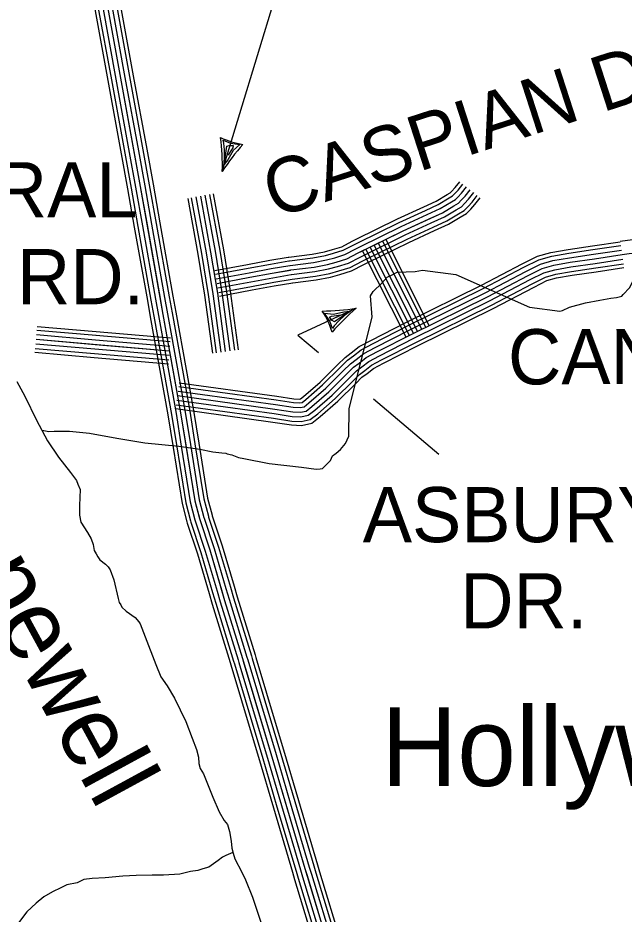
# Model space of a CAD drawing. Extents: x 1551132 to 1791609, y 378168 to 563823.
# Drawn here: x 1653929 to 1657991, y 420262 to 426270 of the extents above; entities that cross this region are included whole.
import ezdxf

# ---------------------------------------------------------------- set-up
doc = ezdxf.new("R2010")
doc.units = 0
for name, color, linetype in [('DESIGN - DRAINAGE - Bridges and Cross Drains Size Text', 7, 'Continuous'), ('DESIGN - ROW - Right-of-Way and Easement Labels', 7, 'Continuous'), ('DESIGN - TRANSPORTATION - Text', 7, 'Continuous'), ('SURVEY - CENTERLINE - Preliminary Text', 7, 'Continuous'), ('SURVEY - PROPERTY - Owners', 7, 'Continuous'), ('SURVEY - TRANSPORTATION - Roads', 7, 'Continuous'), ('SURVEY - VEGETATION - Features with Text', 7, 'Continuous')]:
    doc.layers.add(name, color=color, linetype=linetype)

msp = doc.modelspace()

# ---------------------------------------------------------------- linework, layer by layer
at = {"layer": 'DESIGN - ROW - Right-of-Way and Easement Labels'}
for p, q in [((1655298.56, 425240.72), (1655734.434, 426681.149)), ((1655309.568, 425429.383), (1655304.785, 425449.717)), ((1655304.785, 425449.717), (1655353.1, 425430.241)), ((1655313.501, 425384.948), (1655309.568, 425429.383)), ((1655311.834, 425286.729), (1655328.351, 425411.391)), ((1655313.943, 425332.655), (1655313.501, 425384.948)), ((1655328.351, 425411.391), (1655344.975, 425415.074)), ((1655370.875, 425380.39), (1655336.292, 425319.03)), ((1655351.584, 425371.965), (1655338.342, 425350.556)), ((1655344.975, 425415.074), (1655372.508, 425414.258)), ((1655370.125, 425399.474), (1655351.584, 425371.965)), ((1655353.1, 425430.241), (1655415.557, 425420.841)), ((1655372.508, 425414.258), (1655370.125, 425399.474)), ((1655415.557, 425420.841), (1655370.875, 425380.39)), ((1655309.085, 425274.312), (1655313.943, 425332.655)), ((1655336.292, 425319.03), (1655311.834, 425286.729)), ((1656019.042, 424237.76), (1655984.202, 424290.445)), ((1655984.202, 424290.445), (1656044.158, 424284.345)), ((1656044.158, 424284.345), (1656112.89, 424299.745)), ((1656153.256, 424303.212), (1656049.608, 424232.002)), ((1656112.89, 424299.745), (1656153.256, 424303.212)), ((1656164.314, 424309.479), (1656117.74, 424274.02)), ((1656017.917, 424262.878), (1656030.492, 424271.011)), ((1656035.742, 424241.885), (1656017.917, 424262.878)), ((1656036.925, 424188.834), (1656019.042, 424237.76)), ((1656030.492, 424271.011), (1656063.333, 424275.653)), ((1656049.608, 424232.002), (1656035.742, 424241.885)), ((1656079.191, 424238.677), (1656048.817, 424206.001)), ((1656063.333, 424275.653), (1656088.099, 424280.161)), ((1656117.74, 424274.02), (1656079.191, 424238.677)), ((1656048.817, 424206.001), (1656036.925, 424188.834))]:
    msp.add_line(p, q, dxfattribs=at)
for points in [[(1656196.313, 424324.154), (1655805.639, 424143.799), (1655943.352, 424027.246)], [(1656311.244, 423715.905), (1656749.608, 423344.921)]]:
    msp.add_lwpolyline(points, dxfattribs=at)
for centre, radius, start, end in [((1653746.777, 425280.525), 1552.315, 358.5310611, 6.9588389), ((1655518.373, 425948.283), 532.286, 244.313675, 261.1720722), ((1656467.354, 424495.075), 1386.374, 138.0242889, 147.4628278), ((1655967.543, 425691.491), 1386.33, 270.0587833, 279.4973222), ((1655523.589, 424013.634), 532.306, 16.3489444, 33.2073417), ((1657205.819, 423145.003), 1552.278, 130.5682417, 138.9960194)]:
    msp.add_arc(centre, radius, start, end, dxfattribs=at)
at = {"layer": 'DESIGN - TRANSPORTATION - Text'}
for points in [[(1656640.203, 424579.503), (1656863.748, 424550.394), (1657358.069, 424329.972), (1657561.49, 424303.371), (1657579.006, 424309.263), (1657625.146, 424330.972), (1657733.336, 424360.256), (1657829.442, 424377.598), (1657903.532, 424391.099), (1657939.547, 424394.849), (1657975.613, 424404.607), (1657985.688, 424416.558), (1658027.979, 424460.334), (1658050.253, 424502.243), (1658056.628, 424525.502), (1658049.003, 424590.971)], [(1656292.144, 424406.415), (1656310.486, 424436.216), (1656366.843, 424491.909), (1656403.109, 424531.718), (1656437.208, 424547.502), (1656471.324, 424565.286), (1656591.354, 424570.444), (1656640.203, 424579.503)], [(1654090.445, 423505.798), (1654137.103, 423497.032), (1654171.11, 423498.798), (1654213.126, 423500.507), (1654275.116, 423500.065), (1654409.03, 423487.098), (1654590.792, 423451.747), (1654778.588, 423422.372), (1655006.432, 423398.721), (1655148.296, 423379.687), (1655236.177, 423361.037), (1655296.125, 423354.595), (1655322.117, 423352.412), (1655332.091, 423348.337), (1655362.032, 423340.111), (1655407.923, 423323.761), (1655443.872, 423315.486), (1655611.643, 423282.252), (1655829.48, 423258.668), (1655927.386, 423243.951), (1655955.41, 423247.759), (1655969.418, 423249.659), (1655987.534, 423267.56), (1656023.767, 423303.361), (1656037.966, 423333.312), (1656062.083, 423351.17), (1656090.249, 423377.013), (1656124.506, 423416.839), (1656145.539, 423465.957), (1656149.072, 423650.837), (1656303.919, 424264.444), (1656292.144, 424406.415)], [(1653922.075, 423831.624), (1653975.44, 423735.088), (1654054.38, 423574.267), (1654127.47, 423435.522), (1654200.743, 423324.827), (1654282.066, 423222.083), (1654321.723, 423169.715), (1654329.548, 423143.622), (1654345.331, 423109.455), (1654340.623, 423001.31), (1654342.198, 422937.192), (1654349.881, 422889.057), (1654395.438, 422820.631), (1654419.154, 422778.388), (1654432.904, 422740.228), (1654440.645, 422700.111), (1654452.495, 422677.994), (1654464.37, 422657.876), (1654478.236, 422637.742), (1654516.035, 422607.425), (1654533.918, 422589.266), (1654547.784, 422569.141), (1654571.35, 422502.864), (1654600.533, 422378.452), (1654606.349, 422350.368), (1654618.257, 422336.26), (1654626.149, 422320.176), (1654653.965, 422291.934)], [(1654653.965, 422291.934), (1654715.68, 422249.432), (1654739.496, 422221.215), (1654747.404, 422207.14), (1654780.837, 422120.762), (1654853.627, 421935.941), (1654887.068, 421851.572), (1654928.675, 421791.179), (1654978.132, 421708.693), (1655055.114, 421553.898), (1655096.379, 421441.42), (1655125.878, 421365.084), (1655139.536, 421312.908), (1655141.261, 421270.824), (1655151.044, 421238.706), (1655172.811, 421202.489), (1655235.784, 421045.793), (1655277.133, 420947.34), (1655310.749, 420889.005), (1655332.582, 420862.805), (1655338.473, 420846.738), (1655346.265, 420814.628), (1655357.839, 420750.443), (1655363.539, 420704.334), (1655371.314, 420670.216), (1655383.064, 420632.074), (1655430.488, 420543.596), (1655454.145, 420491.345), (1655500.719, 420374.917)], [(1655370.239, 420674.916), (1655323.215, 420654.533), (1655299.141, 420642.682), (1655271, 420620.848), (1655208.709, 420577.222), (1655168.635, 420565.48), (1655134.561, 420553.705), (1655086.529, 420548.038), (1655014.397, 420528.512), (1654904.366, 420523.287), (1654828.36, 420521.82), (1654722.362, 420520.57), (1654632.323, 420515.195), (1654514.267, 420506.02), (1654426.236, 420500.636), (1654370.187, 420493.019), (1654326.047, 420471.294), (1654255.965, 420457.768), (1654215.833, 420438.018), (1654159.659, 420410.375), (1654103.452, 420378.716), (1654051.17, 420335.015), (1653988.788, 420277.364), (1653851.608, 420096.042)], [(1655500.719, 420374.917), (1655690.564, 419808.285)]]:
    msp.add_lwpolyline(points, dxfattribs=at)
at = {"layer": 'SURVEY - CENTERLINE - Preliminary Text'}
for points in [[(1654441.18, 426342.44), (1654530.686, 425850.51)], [(1654465.497, 426346.865), (1654555.003, 425854.935)], [(1654495.996, 426352.415), (1654585.502, 425860.485)], [(1654526.495, 426357.965), (1654748.123, 425139.85), (1654901.16, 424281.019), (1655019.357, 423622.835), (1655113.938, 423032.953), (1655147.22, 422906.475), (1655214.094, 422703.62), (1655314.191, 422364.261), (1655434.022, 421974.676), (1655624.458, 421338.109), (1655852.144, 420567.031), (1656034.773, 419964.59)], [(1654526.495, 426357.965), (1654616.001, 425866.036)], [(1654556.994, 426363.515), (1654646.5, 425871.586)], [(1654587.494, 426369.065), (1654677, 425877.136)], [(1654612.793, 426373.666), (1654702.299, 425881.736)], [(1654554.994, 425854.952), (1654644.5, 425363.014)], [(1654585.493, 425860.502), (1654674.999, 425368.564)], [(1654615.993, 425866.052), (1654705.499, 425374.114)], [(1654646.492, 425871.602), (1654735.998, 425379.665)], [(1654676.991, 425877.153), (1654766.497, 425385.215)], [(1654702.291, 425881.753), (1654791.797, 425389.815)], [(1654530.678, 425850.527), (1654620.184, 425358.589)], [(1654705.499, 425374.131), (1654748.123, 425139.85), (1654794.063, 424882.027)], [(1654735.998, 425379.681), (1654778.63, 425145.342), (1654824.579, 424887.468)], [(1654766.497, 425385.231), (1654809.138, 425150.842), (1654855.103, 424892.902)], [(1654791.797, 425389.832), (1654834.446, 425155.392), (1654880.419, 424897.419)], [(1654620.184, 425358.606), (1654662.783, 425124.483), (1654708.69, 424866.809)], [(1654644.5, 425363.031), (1654687.107, 425128.858), (1654733.023, 424871.151)], [(1654674.999, 425368.581), (1654717.615, 425134.358), (1654763.547, 424876.585)], [(1654855.103, 424892.919), (1654942.818, 424400.664)], [(1654880.419, 424897.435), (1654968.134, 424405.181)], [(1654708.69, 424866.826), (1654796.404, 424374.572)], [(1654733.023, 424871.168), (1654820.737, 424378.913)], [(1654763.547, 424876.601), (1654851.261, 424384.347)], [(1654794.063, 424882.043), (1654881.777, 424389.789)], [(1654824.579, 424887.485), (1654912.293, 424395.231)], [(1654796.404, 424374.597), (1654815.804, 424265.752), (1654884.66, 423882.309)], [(1654820.737, 424378.93), (1654840.128, 424270.102), (1654908.985, 423886.676)], [(1654851.261, 424384.364), (1654870.644, 424275.561), (1654939.501, 423892.151)], [(1654881.777, 424389.805), (1654901.16, 424281.019), (1654970.008, 423897.634)], [(1654912.293, 424395.247), (1654931.676, 424286.478), (1655000.516, 423903.118)], [(1654942.818, 424400.681), (1654962.192, 424291.936), (1655031.032, 423908.593)], [(1654968.134, 424405.189), (1654987.508, 424296.47), (1655056.34, 423913.143)], [(1654884.66, 423882.325), (1654933.867, 423608.302), (1654968.692, 423391.088)], [(1654908.985, 423886.692), (1654958.234, 423612.443), (1654993.099, 423395.004)], [(1654939.501, 423892.167), (1654988.791, 423617.643), (1655023.707, 423399.913)], [(1654970.008, 423897.651), (1655019.357, 423622.835), (1655054.315, 423404.821)], [(1655000.516, 423903.134), (1655049.923, 423628.027), (1655084.922, 423409.73)], [(1655031.032, 423908.609), (1655080.481, 423633.227), (1655115.53, 423414.638)], [(1655056.34, 423913.151), (1655105.838, 423637.536), (1655140.921, 423418.713)], [(1654968.683, 423391.104), (1655028.99, 423015.011), (1655061.481, 422891.574)], [(1654993.091, 423395.021), (1655053.206, 423020.12), (1655085.38, 422897.858)], [(1655023.699, 423399.929), (1655083.572, 423026.536), (1655115.363, 422905.75)], [(1655054.306, 423404.838), (1655113.938, 423032.953), (1655145.337, 422913.642)], [(1655084.914, 423409.746), (1655144.304, 423039.37), (1655175.311, 422921.534)], [(1655115.521, 423414.655), (1655174.67, 423045.787), (1655205.294, 422929.426)], [(1655140.912, 423418.73), (1655199.861, 423051.104), (1655230.16, 422935.967)], [(1655145.329, 422913.658), (1655147.22, 422906.475), (1655214.094, 422703.62), (1655293.025, 422436.021)], [(1655175.303, 422921.55), (1655176.953, 422915.283), (1655243.685, 422712.862), (1655322.758, 422444.788)], [(1655205.286, 422929.451), (1655206.694, 422924.092), (1655273.284, 422722.103), (1655352.49, 422453.563)], [(1655230.152, 422936.001), (1655231.36, 422931.401), (1655297.833, 422729.77), (1655377.156, 422460.838)], [(1655061.472, 422891.574), (1655064.039, 422881.833), (1655131.312, 422677.769), (1655209.852, 422411.487)], [(1655085.372, 422897.866), (1655087.747, 422888.858), (1655154.903, 422685.136), (1655233.56, 422418.479)], [(1655115.354, 422905.767), (1655117.488, 422897.666), (1655184.503, 422694.378), (1655263.292, 422427.254)], [(1655293.017, 422436.038), (1655314.191, 422364.261), (1655434.022, 421974.676), (1655439.055, 421957.833)], [(1655322.749, 422444.813), (1655343.874, 422373.203), (1655463.687, 421983.668), (1655468.754, 421966.709)], [(1655352.482, 422453.58), (1655373.556, 422382.145), (1655493.353, 421992.668), (1655498.453, 421975.584)], [(1655377.148, 422460.855), (1655398.181, 422389.57), (1655517.961, 422000.126), (1655523.094, 421982.951)], [(1655209.844, 422411.495), (1655231.16, 422339.243), (1655351.04, 421949.508), (1655355.973, 421932.999)], [(1655233.551, 422418.495), (1655254.826, 422346.377), (1655374.69, 421956.683), (1655379.656, 421940.083)], [(1655263.284, 422427.262), (1655284.509, 422355.319), (1655404.356, 421965.684), (1655409.355, 421948.958)], [(1655409.355, 421948.967), (1655552.66, 421469.937)], [(1655439.055, 421957.85), (1655582.359, 421478.821)], [(1655468.754, 421966.734), (1655612.059, 421487.705)], [(1655498.453, 421975.617), (1655641.758, 421496.588)], [(1655523.086, 421982.993), (1655666.391, 421503.963)], [(1655355.982, 421932.991), (1655499.286, 421453.962)], [(1655379.656, 421940.083), (1655522.961, 421461.054)], [(1655552.66, 421469.954), (1655594.742, 421329.275), (1655694.732, 420990.658)], [(1655582.359, 421478.838), (1655624.458, 421338.109), (1655724.464, 420999.442)], [(1655612.059, 421487.721), (1655654.174, 421346.943), (1655754.197, 421008.225)], [(1655641.758, 421496.605), (1655683.89, 421355.776), (1655783.921, 421017.001)], [(1655666.391, 421503.98), (1655708.54, 421363.101), (1655808.587, 421024.284)], [(1655499.286, 421453.979), (1655541.335, 421313.4), (1655641.299, 420974.883)], [(1655522.961, 421461.07), (1655565.026, 421320.442), (1655665.007, 420981.883)], [(1655694.723, 420990.675), (1655822.445, 420558.147), (1655836.728, 420511.029)], [(1655724.456, 420999.458), (1655852.144, 420567.031), (1655866.394, 420520.021)], [(1655754.189, 421008.242), (1655881.844, 420575.914), (1655896.06, 420529.013)], [(1655783.913, 421017.017), (1655911.543, 420584.806), (1655925.726, 420538.005)], [(1655808.579, 421024.301), (1655936.176, 420592.173), (1655950.334, 420545.472)], [(1655641.291, 420974.899), (1655769.071, 420542.171), (1655783.413, 420494.862)], [(1655664.999, 420981.9), (1655792.746, 420549.255), (1655807.062, 420502.037)], [(1655836.728, 420511.046), (1655981.783, 420032.533)], [(1655866.394, 420520.038), (1656011.449, 420041.525)], [(1655896.06, 420529.03), (1656041.115, 420050.517)], [(1655925.726, 420538.021), (1656070.781, 420059.509)], [(1655950.334, 420545.488), (1656095.388, 420066.976)], [(1655783.413, 420494.879), (1655928.467, 420016.366)], [(1655807.062, 420502.054), (1655952.117, 420023.541)]]:
    msp.add_lwpolyline(points, dxfattribs=at)
at = {"layer": 'SURVEY - PROPERTY - Owners'}
for points in [[(1657964.355, 424772.95), (1658014.254, 424780.417), (1658101.669, 424790.234), (1658172.984, 424790.551), (1658272.29, 424788.034), (1658429.636, 424777.117), (1658675.664, 424752.184), (1658958.682, 424743.975), (1659039.614, 424743.975), (1659192.935, 424744.025), (1659357.473, 424739.192), (1659484.203, 424726.35), (1659666.682, 424709.65), (1659783.313, 424701.483), (1659841.311, 424702.991), (1659885.194, 424707.675), (1659971.65, 424729.784), (1660129.38, 424799.386), (1660295.743, 424880.838), (1660430.006, 424974.674)], [(1657977.772, 424683.24), (1658026.029, 424690.457), (1658106.944, 424699.549), (1658172.034, 424699.832), (1658267.998, 424697.407), (1658421.92, 424686.723), (1658669.772, 424661.606), (1658957.365, 424653.264), (1659039.63, 424653.264), (1659191.618, 424653.315), (1659351.565, 424648.615), (1659475.495, 424636.056), (1659659.382, 424619.231), (1659781.321, 424610.689), (1659847.32, 424612.406), (1659901.327, 424618.172), (1660001.399, 424643.765), (1660167.645, 424717.125), (1660341.941, 424802.461)]]:
    msp.add_lwpolyline(points, dxfattribs=at)
at = {"layer": 'SURVEY - TRANSPORTATION - Roads'}
for points in [[(1656648.62, 425003.322), (1656732.309, 425041.907), (1656805.583, 425085.9), (1656826.282, 425097.433), (1656835.124, 425107.192), (1656858.948, 425132.684), (1656889.497, 425172.002)], [(1656659.386, 424979.963), (1656744.351, 425019.14), (1656818.466, 425063.632), (1656842.499, 425077.033), (1656854.048, 425089.775), (1656878.539, 425115.975), (1656909.805, 425156.227)], [(1656672.361, 424951.813), (1656758.859, 424991.697), (1656833.999, 425036.798), (1656862.04, 425052.432), (1656876.856, 425068.774), (1656902.147, 425095.842), (1656934.28, 425137.201)], [(1655321.075, 424034.088), (1655267.618, 424424.215), (1655222.695, 424700.722), (1655154.163, 425075.449)], [(1655321.075, 424034.088), (1655267.618, 424424.215), (1655222.695, 424700.722), (1655154.163, 425075.449)], [(1655351.791, 424038.296), (1655298.276, 424428.807), (1655253.244, 424705.997), (1655184.654, 425081.024)], [(1655382.499, 424042.505), (1655328.942, 424433.398), (1655283.793, 424711.272), (1655215.153, 425086.607)], [(1655407.982, 424045.997), (1655354.375, 424437.207), (1655309.134, 424715.647), (1655240.444, 425091.232)], [(1655263.869, 424490.3), (1655483.98, 424531.384), (1655632.052, 424558.769), (1655758.107, 424580.244), (1655914.153, 424599.586), (1656004.201, 424617.212), (1656062.242, 424632.979), (1656132.315, 424654.696), (1656208.446, 424694.406), (1656510.956, 424843.251), (1656773.367, 424964.246), (1656849.523, 425009.964), (1656881.589, 425027.84), (1656899.664, 425047.782), (1656925.763, 425075.708), (1656958.762, 425118.184)], [(1656685.344, 424923.662), (1656773.367, 424964.246), (1656849.523, 425009.964), (1656881.589, 425027.84), (1656899.664, 425047.782), (1656925.763, 425075.708), (1656958.762, 425118.184)], [(1656698.327, 424895.511), (1656787.875, 424936.796), (1656865.048, 424983.13), (1656901.139, 425003.248), (1656922.472, 425026.79), (1656949.379, 425055.574), (1656983.245, 425099.167)], [(1656711.301, 424867.361), (1656802.383, 424909.353), (1656880.581, 424956.296), (1656920.68, 424978.647), (1656945.279, 425005.789), (1656972.987, 425035.44), (1657007.72, 425080.141)], [(1655235.161, 424022.313), (1655181.854, 424411.373), (1655137.238, 424685.963), (1655068.865, 425059.848)], [(1655259.652, 424025.671), (1655206.295, 424415.031), (1655161.596, 424690.172), (1655093.173, 425064.29)], [(1655290.359, 424029.879), (1655236.961, 424419.623), (1655192.145, 424695.447), (1655123.672, 425069.873)], [(1656721.651, 424844.91), (1656813.957, 424887.469), (1656892.964, 424934.896), (1656936.263, 424959.038), (1656963.471, 424989.056), (1656991.812, 425019.381), (1657027.236, 425064.983)], [(1656195.922, 424786.008), (1656473.224, 424922.445), (1656648.636, 425003.331)], [(1656207.272, 424762.933), (1656484.29, 424899.228), (1656659.403, 424979.972)], [(1656220.963, 424735.115), (1656497.623, 424871.244), (1656672.377, 424951.821)], [(1656234.646, 424707.298), (1656510.956, 424843.251), (1656685.36, 424923.67)], [(1656248.329, 424679.48), (1656524.289, 424815.259), (1656698.343, 424895.52)], [(1656262.02, 424651.663), (1656537.622, 424787.275), (1656711.318, 424867.369)], [(1656272.928, 424629.487), (1656548.255, 424764.958), (1656721.668, 424844.918)], [(1655741.124, 424666.338), (1655745.399, 424667.063), (1655900.32, 424686.264), (1655984.252, 424702.689), (1656037.751, 424717.223), (1656098.782, 424736.14), (1656168.797, 424772.658), (1656195.939, 424786.016)], [(1656662.936, 424197.518), (1656371.634, 424775.366)], [(1656685.893, 424209.093), (1656394.592, 424786.942)], [(1655002.974, 423768.406), (1655655.017, 423678.329), (1655773.523, 423660.003), (1655819.53, 423657.862), (1655847.004, 423663.595), (1655878.779, 423688.496), (1655991.768, 423786.915), (1656109.482, 423903.818), (1656157.306, 423951.311), (1656196.855, 423980.245), (1656246.704, 424019.421), (1656323.518, 424060.572), (1656554.38, 424177.934), (1657061.06, 424427.916), (1657333.412, 424570.811), (1657430.518, 424619.946), (1657512.966, 424642.847), (1657624.972, 424662.731), (1657787.443, 424686.115), (1657973.188, 424713.899)], [(1655007.216, 423799.115), (1655659.509, 423709.005), (1655776.623, 423690.887), (1655817.047, 423689.012), (1655833.588, 423692.463), (1655859.029, 423712.405), (1655970.643, 423809.632), (1656087.632, 423925.81), (1656137.114, 423974.953), (1656178.122, 424004.946), (1656229.679, 424045.464), (1656309.169, 424088.057), (1656540.497, 424205.651), (1657046.993, 424455.542), (1657319.212, 424598.37), (1657419.268, 424648.989), (1657506.091, 424673.106), (1657620.055, 424693.348), (1657782.943, 424716.782), (1657968.597, 424744.558)], [(1655010.599, 423823.599), (1655663.084, 423733.464), (1655779.089, 423715.521), (1655815.064, 423713.846), (1655822.88, 423715.48), (1655843.28, 423731.464), (1655953.802, 423827.733), (1656070.216, 423943.353), (1656121.023, 423993.804), (1656163.189, 424024.646), (1656216.104, 424066.231), (1656297.736, 424109.965), (1656529.43, 424227.76), (1657035.785, 424477.575), (1657307.896, 424620.346), (1657410.293, 424672.156), (1657500.616, 424697.24), (1657616.13, 424717.757), (1657779.351, 424741.241), (1657964.939, 424769)], [(1655745.407, 424640.979), (1655749.124, 424641.604), (1655904.37, 424660.846), (1655990.102, 424677.63), (1656044.934, 424692.522), (1656108.607, 424712.264), (1656180.422, 424749.716), (1656207.288, 424762.941)], [(1655750.574, 424610.412), (1655753.615, 424610.928), (1655909.262, 424630.221), (1655997.151, 424647.421), (1656053.583, 424662.755), (1656120.465, 424683.48), (1656194.43, 424722.065), (1656220.98, 424735.123)], [(1656552.205, 424141.7), (1656260.904, 424719.548)], [(1656579.888, 424155.65), (1656288.586, 424733.498)], [(1656607.57, 424169.609), (1656316.269, 424747.457)], [(1656607.57, 424169.609), (1656316.269, 424747.457)], [(1656635.253, 424183.568), (1656343.952, 424761.416)], [(1654994.491, 423706.988), (1655646.034, 423616.977), (1655767.323, 423598.218), (1655824.497, 423595.56), (1655873.854, 423605.86), (1655918.294, 423640.695), (1656034.017, 423741.497), (1656153.164, 423859.817), (1656197.671, 423904.027), (1656234.32, 423930.827), (1656280.753, 423967.32), (1656352.201, 424005.604), (1656582.146, 424122.499), (1657089.176, 424372.648), (1657361.811, 424515.693), (1657453.034, 424561.845), (1657526.716, 424582.312), (1657634.805, 424601.512), (1657796.443, 424624.763), (1657982.355, 424652.581)], [(1654998.733, 423737.697), (1655650.526, 423647.653), (1655770.423, 423629.111), (1655822.013, 423626.711), (1655860.429, 423634.728), (1655898.537, 423664.595), (1656012.892, 423764.206), (1656131.323, 423881.818), (1656177.488, 423927.669), (1656215.588, 423955.536), (1656263.728, 423993.371), (1656337.86, 424033.088), (1656568.263, 424150.217), (1657075.118, 424400.282), (1657347.611, 424543.252), (1657441.776, 424590.895), (1657519.841, 424612.579), (1657629.888, 424632.122), (1657791.943, 424655.439), (1657977.772, 424683.24)], [(1654998.733, 423737.697), (1655650.526, 423647.653), (1655770.423, 423629.111), (1655822.013, 423626.711), (1655860.429, 423634.728), (1655898.537, 423664.595), (1656012.892, 423764.206), (1656131.323, 423881.818), (1656177.488, 423927.669), (1656215.588, 423955.536), (1656263.728, 423993.371), (1656337.86, 424033.088), (1656568.263, 424150.217), (1657075.118, 424400.282), (1657347.611, 424543.252), (1657441.776, 424590.895), (1657519.841, 424612.579), (1657629.888, 424632.122), (1657791.943, 424655.439), (1657977.772, 424683.24)], [(1655247.777, 424576.527), (1655467.955, 424617.628), (1655616.71, 424645.137), (1655741.024, 424666.321)], [(1655755.74, 424579.844), (1655758.107, 424580.244), (1655914.153, 424599.586), (1656004.201, 424617.212), (1656062.242, 424632.979), (1656132.315, 424654.696), (1656208.446, 424694.406), (1656234.663, 424707.306)], [(1655760.907, 424549.277), (1655762.599, 424549.56), (1655919.045, 424568.952), (1656011.251, 424587.003), (1656070.9, 424603.203), (1656144.165, 424625.912), (1656222.463, 424666.747), (1656248.346, 424679.489)], [(1655766.073, 424518.709), (1655767.09, 424518.884), (1655923.936, 424538.326), (1656018.301, 424556.794), (1656079.549, 424573.436), (1656156.023, 424597.128), (1656236.471, 424639.096), (1656262.037, 424651.671)], [(1656530.139, 424130.574), (1656238.837, 424708.423)], [(1654986.733, 423650.803), (1655637.818, 423560.859), (1655761.656, 423541.709), (1655829.046, 423538.567), (1655898.403, 423553.042), (1655954.435, 423596.96), (1656072.666, 423699.946), (1656193.13, 423819.574), (1656234.604, 423860.767), (1656268.595, 423885.626), (1656311.902, 423919.669), (1656378.45, 423955.32), (1656607.545, 424071.781), (1657114.9, 424322.096), (1657387.785, 424465.275), (1657473.625, 424508.702), (1657539.29, 424526.944), (1657643.804, 424545.503), (1657804.676, 424568.645), (1657990.746, 424596.487)], [(1654990.249, 423676.278), (1655641.543, 423586.301), (1655764.223, 423567.334), (1655826.98, 423564.409), (1655887.27, 423576.993), (1655938.044, 423616.786), (1656055.141, 423718.78), (1656175.013, 423837.825), (1656217.863, 423880.384), (1656253.053, 423906.127), (1656297.777, 423941.278), (1656366.551, 423978.12), (1656596.029, 424094.782), (1657103.242, 424345.022), (1657376.011, 424488.134), (1657464.284, 424532.802), (1657533.59, 424552.053), (1657639.721, 424570.895), (1657800.942, 424594.096), (1657986.946, 424621.921)], [(1655252.494, 424551.251), (1655472.655, 424592.344), (1655621.21, 424619.82), (1655745.349, 424640.962)], [(1655258.177, 424520.776), (1655478.322, 424561.86), (1655626.627, 424589.294), (1655750.549, 424610.403)], [(1655770.19, 424494.342), (1655770.673, 424494.417), (1655927.828, 424513.901), (1656023.917, 424532.71), (1656086.449, 424549.694), (1656165.464, 424574.186), (1656247.646, 424617.045), (1656272.945, 424629.496)], [(1655263.869, 424490.3), (1655483.98, 424531.384), (1655632.052, 424558.769), (1655755.757, 424579.844)], [(1655269.56, 424459.824), (1655489.638, 424500.909), (1655637.476, 424528.243), (1655760.965, 424549.285)], [(1655275.243, 424429.348), (1655495.305, 424470.424), (1655642.893, 424497.717), (1655766.165, 424518.726)], [(1655279.776, 424405.056), (1655499.821, 424446.124), (1655647.218, 424473.383), (1655770.323, 424494.359)], [(1654452.171, 424141.274), (1654055.963, 424175.233)], [(1654454.287, 424165.899), (1654058.08, 424199.858)], [(1654945.017, 424036.804), (1654050.672, 424113.456)], [(1654446.879, 424079.497), (1654050.672, 424113.456)], [(1654449.529, 424110.381), (1654053.322, 424144.34)], [(1654947.667, 424067.689), (1654449.512, 424110.381)], [(1654950.309, 424098.581), (1654452.154, 424141.274)], [(1654952.426, 424123.207), (1654454.271, 424165.899)], [(1654441.588, 424017.72), (1654045.38, 424051.679)], [(1654444.229, 424048.613), (1654048.022, 424082.572)], [(1654945.017, 424036.804), (1654446.862, 424079.497)], [(1654439.388, 423992.095), (1654043.18, 424026.054)], [(1654937.526, 423949.402), (1654439.371, 423992.095)], [(1654939.726, 423975.028), (1654441.571, 424017.72)], [(1654942.367, 424005.92), (1654444.212, 424048.613)]]:
    msp.add_lwpolyline(points, dxfattribs=at)

# ---------------------------------------------------------------- texts
at = {"layer": 'DESIGN - DRAINAGE - Bridges and Cross Drains Size Text'}
msp.add_text('Hopewell', height=475.0068, rotation=298.5555944, dxfattribs=at).set_placement((1653220.587, 423243.569))
at = {"layer": 'DESIGN - ROW - Right-of-Way and Easement Labels'}
for s, height, rotation, p in [('CASPIAN DR.', 369.99319, 17.9222194, (1655646.626, 424924.453)), ('GENERAL', 369.9913, 0.0000306, (1652365.145, 424933.052)), ('RD.', 369.9913, 0.0000306, (1653922.633, 424350.545)), ('CANTEBURY', 369.9913, 0.2133694, (1657213.947, 423812.566)), ('ASBURY', 369.9913, 0.0000306, (1656240.128, 422755.188)), ('DR.', 369.9913, 0.0000306, (1656892.796, 422177.382))]:
    msp.add_text(s, height=height, rotation=rotation, dxfattribs=at).set_placement(p)
at = {"layer": 'SURVEY - VEGETATION - Features with Text'}
msp.add_text('Hollywood', height=527.9876, rotation=0.0000306, dxfattribs=at).set_placement((1656363.833, 421120.762))

doc.saveas('drawing.dxf')
